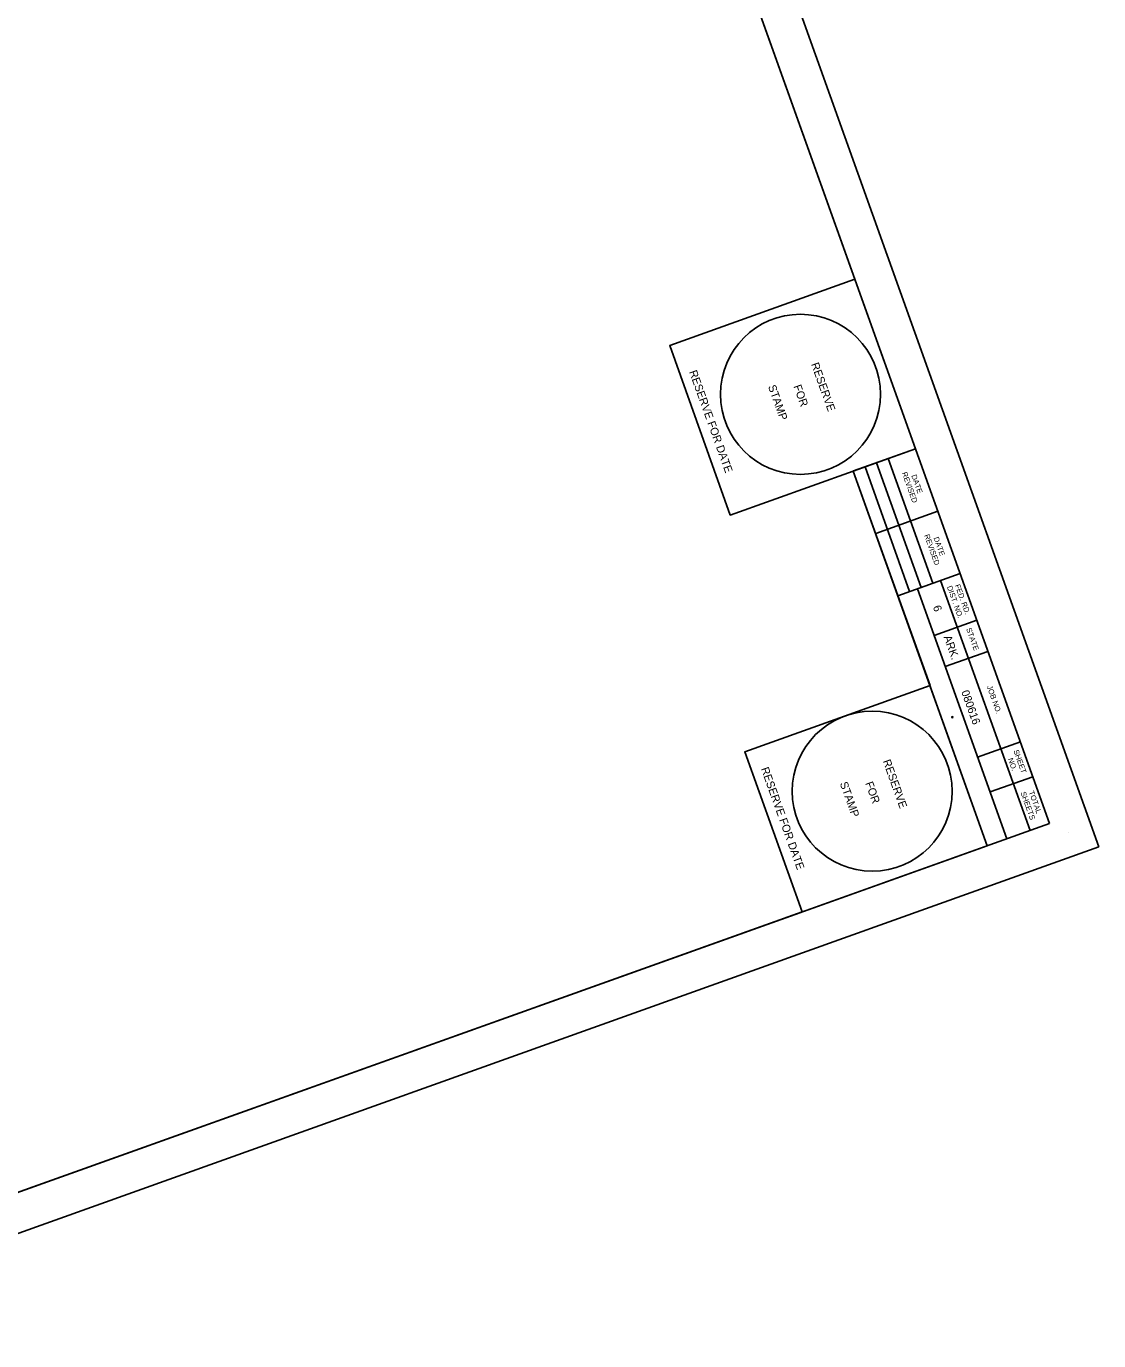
# Model space of a CAD drawing. Extents: x 1051195 to 1052803, y 396319 to 398290.
# Drawn here: x 1051999 to 1052803, y 396319 to 397304 of the extents above; entities that cross this region are included whole.
import ezdxf

# ---------------------------------------------------------------- set-up
doc = ezdxf.new("R2010")
doc.units = 0
for name, color, linetype in [('1', 7, 'Continuous'), ('G-ANNO-TEXT', 7, 'Continuous'), ('G-Border-Sheet', 7, 'Continuous'), ('G-No Plot-Anchor', 7, 'Continuous'), ('G-No Plot-Border-1', 7, 'Continuous'), ('G-No Plot-Border-2', 7, 'Continuous'), ('G-No Plot-Stamp-1', 7, 'Continuous'), ('G-No Plot-Stamp-2', 7, 'Continuous'), ('G-Table-Major', 7, 'Continuous'), ('G-Table-Minor', 7, 'Continuous')]:
    doc.layers.add(name, color=color, linetype=linetype)

msp = doc.modelspace()

# ---------------------------------------------------------------- linework, layer by layer
at = {"layer": '1'}
msp.add_lwpolyline([(1052803.24, 396689.04), (1052230.79, 398289.76), (1051195.03, 397919.35), (1051767.48, 396318.63)], close=True, dxfattribs=at)
at = {"layer": 'G-ANNO-TEXT'}
msp.add_line((1052780.92, 396700.06), (1052780.92, 396700.06), dxfattribs=at)
msp.add_line((1052780.92, 396700.06), (1052780.92, 396700.06), dxfattribs=at)
at = {"layer": 'G-Border-Sheet'}
for p in [(1052229.16, 398208.68), (1051784.92, 396355.5)]:
    msp.add_line(p, (1052766.37, 396706.49), dxfattribs=at)
at = {"layer": 'G-No Plot-Anchor'}
msp.add_circle((1052693.54, 396786.16), 0.5, dxfattribs=at)
msp.add_circle((1052693.54, 396786.16), 0.5, dxfattribs=at)
at = {"layer": 'G-No Plot-Border-1'}
msp.add_lwpolyline([(1051247.71, 397857.69), (1052229.16, 398208.68), (1052665.91, 396987.41), (1052619.25, 396970.73), (1052676.79, 396809.86), (1052537.9, 396760.19), (1052580.83, 396640.13), (1051784.92, 396355.5)], close=True, dxfattribs=at)
at = {"layer": 'G-No Plot-Border-2'}
msp.add_lwpolyline([(1051247.71, 397857.69), (1052229.16, 398208.68), (1052620.45, 397114.53), (1052481.56, 397064.86), (1052527.02, 396937.74), (1052619.25, 396970.73), (1052652.68, 396877.27), (1052719.72, 396689.8), (1051784.92, 396355.5)], close=True, dxfattribs=at)
msp.add_lwpolyline([(1051247.71, 397857.69), (1052229.16, 398208.68), (1052620.45, 397114.53), (1052481.56, 397064.86), (1052527.02, 396937.74), (1052619.25, 396970.73), (1052652.68, 396877.27), (1052719.72, 396689.8), (1051784.92, 396355.5)], close=True, dxfattribs=at)
at = {"layer": 'G-No Plot-Stamp-1'}
msp.add_circle((1052633.43, 396730.63), 60, dxfattribs=at)
at = {"layer": 'G-No Plot-Stamp-2'}
msp.add_circle((1052579.62, 397028.24), 60, dxfattribs=at)
msp.add_circle((1052579.62, 397028.24), 60, dxfattribs=at)
at = {"layer": 'G-Table-Major'}
for p, q in [((1052619.32, 396970.75), (1052665.91, 396987.41)), ((1052645.48, 396980.11), (1052678.9, 396886.65)), ((1052719.72, 396689.8), (1052619.25, 396970.73)), ((1052699.33, 396893.96), (1052652.68, 396877.27))]:
    msp.add_line(p, q, dxfattribs=at)
at = {"layer": 'G-Table-Minor'}
for p, q in [((1052636.67, 396976.96), (1052670.1, 396883.5)), ((1052628.06, 396973.88), (1052661.48, 396880.42)), ((1052636.04, 396923.9), (1052682.66, 396940.57)), ((1052751.73, 396701.25), (1052684.69, 396888.72)), ((1052734.36, 396695.04), (1052667.32, 396882.51)), ((1052711.85, 396858.93), (1052679.84, 396847.48)), ((1052720.22, 396835.53), (1052688.21, 396824.08)), ((1052744.48, 396767.69), (1052712.47, 396756.24)), ((1052753.85, 396741.51), (1052721.83, 396730.07)), ((1052752.62, 396701.57), (1052752.62, 396701.57)), ((1052752.62, 396701.57), (1052752.62, 396701.57))]:
    msp.add_line(p, q, dxfattribs=at)

# ---------------------------------------------------------------- texts
at = {"layer": 'G-ANNO-TEXT'}
for s, height, p in [('REVISED', 4, (1052655.58, 396969.23)), ('DATE', 4, (1052662.65, 396967.29)), ('REVISED', 4, (1052672.29, 396922.5)), ('DATE', 4, (1052679.36, 396920.56)), ('DIST. NO.', 4, (1052689.35, 396883.92)), ('FED. RD.', 4, (1052695.33, 396885.02)), ('6', 6, (1052678.81, 396868.85)), ('STATE', 4, (1052703.81, 396852.39)), ('ARK.', 6, (1052686.88, 396846.29)), ('JOB NO.', 4, (1052719.27, 396809.17)), ('080616', 6, (1052700.04, 396805.18)), ('SHEET', 4, (1052739.24, 396760.97)), ('NO.', 4, (1052735.08, 396754.78)), ('SHEETS', 4, (1052744.56, 396729.54)), ('TOTAL', 4, (1052750.72, 396730.14))]:
    msp.add_text(s, height=height, rotation=289.67806, dxfattribs=at).set_placement(p)
at = {"layer": 'G-No Plot-Stamp-1'}
for s, p in [('RESERVE FOR DATE', (1052549.87, 396747.51)), ('RESERVE', (1052641.27, 396753.25)), ('STAMP', (1052609.02, 396736.53)), ('FOR ', (1052628.09, 396736.67))]:
    msp.add_text(s, height=6, rotation=289.67806, dxfattribs=at).set_placement(p)
at = {"layer": 'G-No Plot-Stamp-2'}
for s, p in [('RESERVE FOR DATE', (1052496.06, 397045.12)), ('RESERVE FOR DATE', (1052496.06, 397045.12)), ('RESERVE', (1052587.46, 397050.86)), ('RESERVE', (1052587.46, 397050.86)), ('STAMP', (1052555.21, 397034.14)), ('STAMP', (1052555.21, 397034.14)), ('FOR ', (1052574.27, 397034.28)), ('FOR ', (1052574.27, 397034.28))]:
    msp.add_text(s, height=6, rotation=289.67806, dxfattribs=at).set_placement(p)

doc.saveas('drawing.dxf')
